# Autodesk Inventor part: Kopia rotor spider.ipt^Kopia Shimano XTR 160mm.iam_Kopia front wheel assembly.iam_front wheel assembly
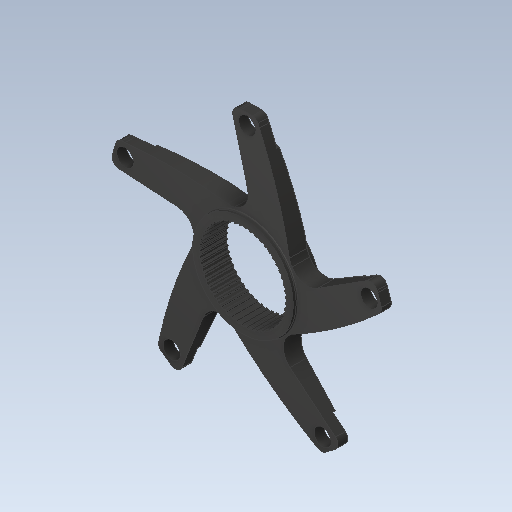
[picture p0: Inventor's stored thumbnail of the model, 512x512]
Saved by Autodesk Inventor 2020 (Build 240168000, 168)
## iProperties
Created: 2017-09
Part Number: Kopia rotor spider.ipt^Kopia Shimano XTR 160mm.iam_Kopia front wheel assembly.iam_front wheel assembly
Material: Ogólny
Document SubType Name: Modeling
Designer: Tomasz
Density: 1 g/cm^3
Appearance: Domyślna
Sending System: SolidWorks 2017
Last Author: Tomasz
Last Saved: 2017-09-11
Author: Tomasz
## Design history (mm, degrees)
feature "rotor spider.ipt"
node "Bryła1"
